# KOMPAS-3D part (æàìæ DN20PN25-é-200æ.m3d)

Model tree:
1. Объединить компоненты:1  (labels: СЕНС DN20PN25-В-200С)

Referenced files in D:\Савин\!СЕНСОР\3D для заказчика\!Новый перечень\СЕНС\4. СЕНС-В-200С\DN20\: СЕНС DN20PN25-В-200С.a3d
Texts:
  СЕНС DN20PN25-В-200С
  ООО НПП Сенсор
